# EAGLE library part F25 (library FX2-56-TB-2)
SubD-Buchse korrigiert und verschönert
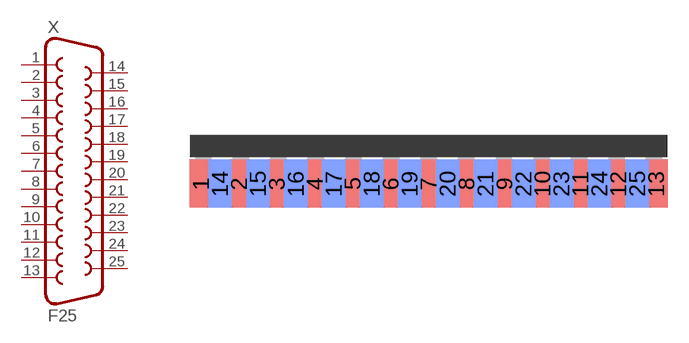
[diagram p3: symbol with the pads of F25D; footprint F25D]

Designator prefix X

## F25D  [F25D]
1  1  pas
2  2  pas
3  3  pas
4  4  pas
5  5  pas
6  6  pas
7  7  pas
8  8  pas
9  9  pas
10  10  pas
11  11  pas
12  12  pas
13  13  pas
14  14  pas
15  15  pas
16  16  pas
17  17  pas
18  18  pas
19  19  pas
20  20  pas
21  21  pas
22  22  pas
23  23  pas
24  24  pas
25  25  pas

## Footprint F25D (pad centres in mm)
SubD korrigiert, Pinabstand: 109 mil (nicht 108) Reichelt D-SUB BU 25 0,14&euro;
smd 1.7 x 3.5: 1 -16.612,-2.249; 2 -13.843,-2.249; 3 -11.074,-2.249; 4 -8.306,-2.249; 5 -5.537,-2.249; 6 -2.769,-2.249; 7 0,-2.249; 8 2.769,-2.249; 9 5.537,-2.249; 10 8.306,-2.249; 11 11.074,-2.249; 12 13.843,-2.249; 13 16.612,-2.249
smd 1.7 x 3.5 bottom: 14 -15.227,-2.249; 15 -12.459,-2.249; 16 -9.69,-2.249; 17 -6.921,-2.249; 18 -4.153,-2.249; 19 -1.384,-2.249; 20 1.384,-2.249; 21 4.153,-2.249; 22 6.921,-2.249; 23 9.69,-2.249; 24 12.459,-2.249; 25 15.227,-2.249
